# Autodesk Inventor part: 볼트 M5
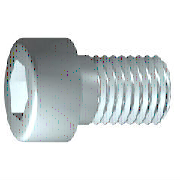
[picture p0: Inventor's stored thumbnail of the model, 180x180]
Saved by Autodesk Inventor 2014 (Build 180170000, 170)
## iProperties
IsCustomPart: 1
Created: 2012-02
Part Number: 볼트 M5
Material: 강철, 연강
Description: 6각머리 태핑 나사
Document SubType Name: Modeling
Standard: KS B 1003
Designer: mduedu
Standards Organization: KS
Language: ko-KR
Size Designation: M 5 x 12
Categories: <MemberInstance><Categories><Category DisplayName="조임쇠" InternalName="e4da775c-781d-43d5-af7c-5136215cf5a6" Mnemonic="FSTN"><Category DisplayName="볼트" InternalN
Density: 1 g/cm^3
Appearance: Steel
Author: mduedu
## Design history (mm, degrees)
sketch "스케치1"
  geometry: L1 (-1.167, 0)-(12, 0); L2 (12, 0)-(12, 2.5); L3 (12, 2.5)-(2, 2.5); L4 (2, 2.5)-(1.509, 2.5); L5 (1.509, 2.5)-(0, 2.5); L6 (0, 2.5)-(0, 4.25); L7 (0, 4.25)-(-5, 4.25); L8 (-5, 4.25)-(-5, 2.309); L9 (-5, 2.309)-(-2.5, 2.309); L10 (-2.5, 2.309)-(-1.167, 0); L11 (-8.4, 0)-(15.4, 0) reference; L12 (0, -0.85)-(0, 5.1) reference; L13 (2, 2.5)-(0, 2.5)
  constraints: 22 end point, 6 parallel, 2 collinear, 2 perpendicular, 1 horizontal, 1 point on line
  dimensions: "d1" = 10 distance from line of L3.end L2 (= GEL); "d2" = 0.49086 distance of L4.end L3.end (computed from GAL); "d3" = 5 distance between parallel lines of L8 L6 (= KOH); "d4" = 2.5 distance of L8.end L9.end (= INTI); "d5" = 60 deg angle of L10 L1; "d6" = 5 diameter of L3 L1 (= GD); "d7" = 5 diameter of L5 L1 (= BDM); "d8" = 4.6188 diameter of L9 L1 (= 1.1547 x SW); "d9" = 8.5 diameter of L7 L1 (= KOD); "d26" = 12 distance between parallel lines of L12 L2 (= NLG)
revolve "본체" sketch "스케치1" stored, may be unused: angle "d10" = 90 deg
sketch "스케치2"
  geometry: L1 (0, -5.95)-(0, 5.95) reference; L2 (-5.95, 0)-(5.95, 0) reference; L3 (2.309, 0)-(1.155, -2); L4 (1.155, -2)-(-1.155, -2); L5 (-1.155, -2)-(-2.309, 0); L6 (-2.309, 0)-(-1.155, 2); L7 (-1.155, 2)-(1.155, 2); L8 (1.155, 2)-(2.309, 0); 2 further points
  constraints: 12 end point, 1 coincident, 1 horizontal alignment, 1 point on line, 12 other
extrude "슬롯" join sketch "스케치2" stored distance "d11" = 10; taper "d12" = 0 deg
workplane "Work Plane1"
fillet "Fillet2" dims "d30" = 0.1 (= R)
body "Solid1"
fillet "모깎기1" dims "d17" = 0.5 (= RR)
feature "스레드" dims "d13" = 10 (= GEL), "d14" = 0
chamfer "모따기1" distance "d15" = 0.49076 (= -0.5 x SPD + 0.5 x GD); stored, may be unused: second distance "d16" = 0.49076 (= GUL), angle "d27" = 45 deg
other parameters: "GD" = 5 (= NND) [user parameter; used in 2 equation terms], "NLG" = 12 [user parameter; used in 1 equation term], "GEL" = 10 [user parameter; used in 2 equation terms], "KOD" = 8.5 [user parameter; used in 1 equation term], "KOH" = 5 [user parameter; used in 1 equation term], "INTI" = 2.5 [user parameter; used in 1 equation term], "GAL" = 0.49076 (= 0.61345 x PTC) [user parameter; used in 1 equation term], "GUL" = 0.49076 (= 0.61345 x PTC) [user parameter; used in 1 equation term], "BDM" = 5 (= NND) [user parameter; used in 1 equation term], "SW" = 4 [user parameter; used in 2 equation terms], "RR" = 0.5 [user parameter; used in 1 equation term], "SPD" = 4.01848 (= NND - 1.2269 x PTC) [user parameter; used in 1 equation term], "d19" = 0, "d28" = 0, "d29" = 0, "R" = 0.1 [user parameter; used in 1 equation term], "PHH" = 0.2 [user parameter], "GD1" = 4.01848 (= THREADDIA - 1.2269 x PTC) [user parameter], "THREADDIA" = 5 [user parameter; used in 1 equation term], "FAWI" = 45 deg [user parameter], "TPU" = 12.5 (computed from PTC) [user parameter], "PTC" = 0.8 [user parameter; used in 5 equation terms], "NND" = 5 [user parameter; used in 3 equation terms], "TOA" = 30 deg [user parameter], "E0" = 4.62 (= 1.155 x SW) [user parameter]
